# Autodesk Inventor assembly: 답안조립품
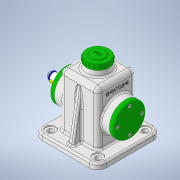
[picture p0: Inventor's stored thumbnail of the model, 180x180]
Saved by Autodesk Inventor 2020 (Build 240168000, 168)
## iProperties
Created: 2021-07
Part Number: 답안조립품
Document SubType Name: Assembly
Designer: Owner
Author: Owner
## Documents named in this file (14)
- C:\Users\Owner\Desktop\710715V1009\답안조립품.iam
- C:\Users\Owner\Desktop\710715V1009\본체.ipt
- C:\Users\Owner\Desktop\710715V1009\V-벨트풀리.ipt
- C:\Users\Owner\Desktop\710715V1009\뒤커버.ipt
- C:\Users\Owner\Desktop\710715V1009\멈춤링 15 x 1.ipt
- C:\Users\Owner\Desktop\710715V1009\베어링 15 x 35 x 11.ipt
- C:\Users\Owner\Desktop\710715V1009\볼트 M4 x 10.ipt
- C:\Users\Owner\Desktop\710715V1009\볼트 M6 x 12.ipt
- C:\Users\Owner\Desktop\710715V1009\상부캡.ipt
- C:\Users\Owner\Desktop\710715V1009\앞커버.ipt
- C:\Users\Owner\Desktop\710715V1009\오일실 15 25 7.ipt
- C:\Users\Owner\Desktop\710715V1009\와셔.ipt
- C:\Users\Owner\Desktop\710715V1009\축.ipt
- C:\Users\Owner\Desktop\710715V1009\키 5 x 5 x 14.ipt
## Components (1 placed, 1 different names)
1. V-벨트풀리:1
